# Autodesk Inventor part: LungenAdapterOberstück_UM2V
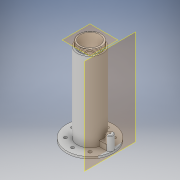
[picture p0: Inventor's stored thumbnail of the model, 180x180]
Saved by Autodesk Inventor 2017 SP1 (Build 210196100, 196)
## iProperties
Part Number: LungenAdapterOberstück_UM2V
Material: Generisch
Document SubType Name: Modeling
Designer: haesner
Density: 1 g/cm^3
Appearance: Vorgabe
Part Number: LungenAdapterOberstück_UM2V_3D-Druck
Author: haesner
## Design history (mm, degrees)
sketch "Skizze1"
  geometry: C1 r 22 at (0, 0); C2 r 9 at (0, 0); 1 further point
  constraints: 2 centre point, 2 coincident
  dimensions: "d0" = 44 diameter of C1; "d1" = 18 diameter of C2
extrude "Extrusion1" new body sketch "Skizze1" distance "d2" = 2; taper "d3" = 0 deg
sketch "Skizze2"
  geometry: C1 r 9 at (0, 0) reference; C2 r 12 at (0, 0); 1 further point
  constraints: 1 centre point, 1 coincident
  dimensions: "d4" = 24 diameter of C2
extrude "Extrusion2" join sketch "Skizze2" distance "d5" = 80; taper "d6" = 0 deg
sketch "Skizze6"
  geometry: L1 (11.667, -11.667)-(-11.667, -11.667); L2 (-11.667, -11.667)-(-11.667, 11.667); L3 (-11.667, 11.667)-(11.667, 11.667); L4 (11.667, 11.667)-(11.667, -11.667); L5 (30.8, 0)-(-30.8, 0) reference; L6 (0, -30.8)-(0, 30.8) reference; L7 (0, -16.5)-(16.5, 0); L8 (16.5, 0)-(0, 16.5); L9 (0, 16.5)-(-16.5, 0); L10 (-16.5, 0)-(0, -16.5); 1 further point
  constraints: 16 end point, 4 parallel, 4 perpendicular, 3 point on line, 1 horizontal, 2 other
  dimensions: "d22" = 16.5 distance of L1.end point (0, 0); "d62" = 16.5 distance from line of L7.start L5
hole "Bohrung2" sketch "Skizze6" at (-11.667, -11.667), (0, -16.5), (-11.667, 11.667), (0, 16.5), (11.667, -11.667), (16.5, 0), (11.667, 11.667) diameter "d23" = 2.9; stored, may be unused: countersink angle "d27" = 90 deg, drill point angle "d29" = 118 deg; dims "d24" = 6, "d25" = 4, "d26" = 2, "d28" = 13.5
sketch "Skizze7"
  geometry: C1 r 10 at (0, 0); C2 r 12 at (0, 0) reference; 1 further point
  constraints: 1 centre point, 1 coincident
  dimensions: "d30" = 20 diameter of C1
extrude "Extrusion5" cut sketch "Skizze7" distance "d31" = 5; taper "d32" = 0 deg
sketch "Skizze8"
  geometry: L1 (9, 77)-(9, 76); L2 (9, 76)-(10, 76); L3 (10, 76)-(10.586, 76.419); L4 (10.586, 76.581)-(10, 77); L5 (10, 77)-(9, 77); L6 (10, 82)-(10, 77) reference; L7 (-12, 77)-(12, 77) reference; A1 r 0.1 centre (10.528, 76.5) between (10.586, 76.419) and (10.586, 76.581); 2 further points
  constraints: 10 end point, 3 point on line, 2 equal length, 2 point on circle, 2 tangent, 1 centre point, 1 collinear, 1 parallel, 1 perpendicular, 1 vertical
  dimensions: "d35" = 1 distance of L1.start L1.end; "d36" = 1 distance of L4.end L1.start; "d38" = 0.7 horizontal distance of point (10.7, 76.5) L4.end; "d39" = 0.1 radius of A1
feature "Spirale1" sketch "Skizze8" pitch "d40" = 1; turns "d42" = 7; dims "d41" = 10, "d43" = 0, angle "d44" = 90 deg, angle "d45" = 90 deg, "d46" = 0, "d47" = 0
workplane "Arbeitsebene2"
feature "Trennen1"
sketch "Skizze9"
  geometry: L1 (-30.8, 0)-(30.8, 0) reference; L2 (19, 3)-(11.619, 3); L3 (19, -3)-(11.619, -3); C1 r 22 at (0, 0) reference; C2 r 12 at (0, 0) reference; A1 r 3 centre (19, 0) between (19, -3) and (19, 3); A2 r 12 centre (0, 0) between (11.619, -3) and (11.619, 3); 1 further point
  constraints: 4 end point, 4 point on circle, 2 centre point, 2 horizontal, 2 tangent, 2 vertical alignment, 1 coincident, 1 parallel, 1 point on line
  dimensions: "d49" = 3 radius of A1
extrude "Extrusion6" join sketch "Skizze9" distance "d50" = 5; taper "d51" = 0 deg
sketch "Skizze10"
  geometry: C1 r 3 at (19, 0); A1 r 3 centre (19, 0) between (19, -3) and (19, 3) reference; 1 further point
  constraints: 1 centre point, 1 coincident, 1 concentric
extrude "Extrusion7" join sketch "Skizze10" distance "d52" = 8; taper "d53" = 0 deg
workplane "Arbeitsebene1"
fillet "Rundung2" dims "d54" = 0.5
sketch "Skizze11"
  geometry: L1 (0, -16.484)-(0, 98.902) reference; L2 (-30.8, 0)-(30.8, 0) reference; C1 r 0.5 at (0, 5); 1 further point
  constraints: 1 centre point, 1 point on line
  dimensions: "d55" = 5 distance from line of L2 C1.centre; "d56" = 1 diameter of C1
extrude "Extrusion8" cut sketch "Skizze11" distance "d57" = 14.25; taper "d58" = 0 deg
sketch "Skizze12"
  geometry: C1 r 0.5 at (0, 0); C2 r 2.5 at (0, 0) reference; 1 further point
  constraints: 1 centre point, 1 coincident
  dimensions: "d59" = 1 diameter of C1
extrude "Extrusion9" cut sketch "Skizze12" distance "d60" = 12; taper "d61" = 0 deg
node "Volumenkörper1"
other parameters: "d7" = 19, "d48" = 5
